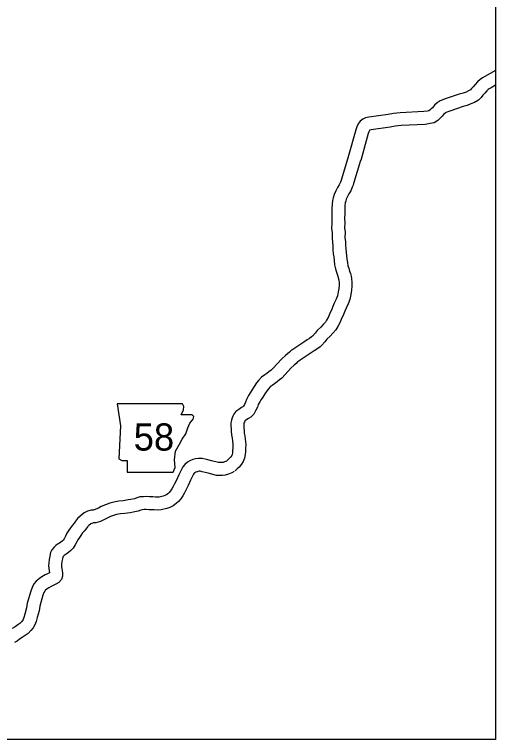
# Model space of a CAD drawing. Extents: x 1377389 to 1380723, y 1168351 to 1170484.
# Drawn here: x 1378167.1 to 1378279.2, y 1169604.3 to 1169773.2 of the extents above; entities that cross this region are included whole.
import ezdxf

# ---------------------------------------------------------------- set-up
doc = ezdxf.new("R2010")
doc.units = 0
doc.layers.add('B_Fill', color=7, linetype='Continuous')
doc.layers.add('B_Text', color=7, linetype='Continuous')

msp = doc.modelspace()

# ---------------------------------------------------------------- linework, layer by layer
at = {"layer": 'B_Fill'}
for points in [[(1378279.16, 1169760.18), (1378276.64, 1169758.77), (1378276.1, 1169758.45), (1378275.56, 1169758.08), (1378274.95, 1169757.52), (1378274.4, 1169756.89), (1378273.94, 1169756.37), (1378273.6, 1169755.97), (1378273.31, 1169755.68), (1378272.86, 1169755.41), (1378272.3, 1169755.16), (1378271.61, 1169754.91), (1378270.71, 1169754.65), (1378267.46, 1169753.55), (1378266.91, 1169753.33), (1378266.27, 1169753.08), (1378265.6, 1169752.65), (1378264.94, 1169752.07), (1378264.48, 1169751.51), (1378264.2, 1169751.21), (1378263.93, 1169750.99), (1378263.64, 1169750.81), (1378263.35, 1169750.73), (1378262.47, 1169750.6), (1378256.97, 1169750.32), (1378255.36, 1169750.14), (1378254.15, 1169749.9), (1378249.64, 1169749.31), (1378248.86, 1169749.13), (1378248.23, 1169748.84), (1378247.64, 1169748.36), (1378247.19, 1169747.73), (1378246.87, 1169747.05), (1378246.63, 1169746.37), (1378244.86, 1169740.03)], [(1378279.16, 1169756.74), (1378278.12, 1169756.16), (1378277.7, 1169755.92), (1378277.44, 1169755.74), (1378277.1, 1169755.42), (1378276.65, 1169754.91), (1378276.21, 1169754.4), (1378275.8, 1169753.92), (1378275.16, 1169753.3), (1378274.26, 1169752.76), (1378273.44, 1169752.38), (1378272.54, 1169752.05), (1378271.6, 1169751.78), (1378268.5, 1169750.74), (1378268.02, 1169750.54), (1378267.64, 1169750.39), (1378267.41, 1169750.25), (1378267.1, 1169749.97), (1378266.72, 1169749.52), (1378266.27, 1169749.05), (1378265.72, 1169748.56), (1378264.84, 1169748.02), (1378263.96, 1169747.79), (1378262.77, 1169747.61), (1378257.21, 1169747.33), (1378255.81, 1169747.17), (1378254.63, 1169746.94), (1378250.18, 1169746.36), (1378249.85, 1169746.28), (1378249.83, 1169746.28), (1378249.79, 1169746.21), (1378249.65, 1169745.92), (1378249.5, 1169745.48), (1378247.75, 1169739.23)], [(1378244.87, 1169740.07), (1378243.28, 1169734.86), (1378243.22, 1169734.64), (1378243.19, 1169734.55), (1378243.04, 1169734.19), (1378242.74, 1169733.51), (1378242.38, 1169732.91), (1378241.99, 1169732.14), (1378241.6, 1169731.28), (1378241.36, 1169730.53), (1378241.22, 1169729.91), (1378241.09, 1169729.02), (1378241.03, 1169728), (1378241.02, 1169726.83), (1378241, 1169725.73), (1378241.02, 1169724.6), (1378240.99, 1169723.39), (1378241.12, 1169722.36), (1378241.08, 1169721.07), (1378241.2, 1169720.09), (1378241.24, 1169719.37), (1378241.3, 1169718.38), (1378241.37, 1169717.47), (1378241.46, 1169716.75), (1378241.55, 1169715.9), (1378241.69, 1169714.92), (1378241.87, 1169713.95), (1378242.09, 1169713.21), (1378242.32, 1169712.49), (1378242.49, 1169711.96), (1378242.62, 1169711.53), (1378242.66, 1169711.3), (1378242.72, 1169710.67), (1378242.72, 1169710.07), (1378242.67, 1169709.37), (1378242.53, 1169708.63), (1378242.32, 1169707.7), (1378242.03, 1169706.9), (1378241.59, 1169705.96), (1378241.29, 1169705.21), (1378241, 1169704.53), (1378240.45, 1169703.38), (1378240.15, 1169702.62), (1378239.81, 1169702.01), (1378239.53, 1169701.53), (1378239.05, 1169701), (1378238.48, 1169700.38), (1378237.64, 1169699.56), (1378237.15, 1169698.94), (1378236.54, 1169698.29), (1378236.33, 1169698.09), (1378235.85, 1169697.74), (1378235.28, 1169697.39), (1378234.54, 1169696.9), (1378231.94, 1169695.16), (1378231.5, 1169694.84), (1378231.16, 1169694.58), (1378230.7, 1169694.17), (1378230.2, 1169693.73), (1378229.42, 1169692.96), (1378227.31, 1169690.73), (1378226.88, 1169690.38), (1378226.38, 1169689.94), (1378225.91, 1169689.58), (1378225.39, 1169689.23), (1378224.68, 1169688.73), (1378223.96, 1169687.95), (1378223.51, 1169687.37), (1378222.93, 1169686.53), (1378222.4, 1169685.71), (1378222.01, 1169685.09), (1378221.61, 1169684.45), (1378221.16, 1169683.55), (1378220.91, 1169682.92), (1378220.66, 1169682.36), (1378220.44, 1169681.96), (1378220.31, 1169681.83), (1378219.97, 1169681.63), (1378219.33, 1169681.18), (1378218.64, 1169680.72), (1378218.21, 1169680.11), (1378217.97, 1169679.65), (1378217.82, 1169679.24), (1378217.64, 1169678.73), (1378217.53, 1169678.04), (1378217.5, 1169677.35), (1378217.55, 1169676.67), (1378217.58, 1169676.1), (1378217.66, 1169675.29), (1378217.78, 1169674.54), (1378217.89, 1169673.9), (1378217.96, 1169672.99), (1378217.94, 1169672.22), (1378217.9, 1169671.52), (1378217.87, 1169671.04), (1378217.81, 1169670.71), (1378217.7, 1169670.45), (1378217.51, 1169670.15), (1378217.3, 1169669.89), (1378216.97, 1169669.61), (1378216.52, 1169669.18)], [(1378247.74, 1169739.19), (1378246.17, 1169734.07), (1378246.11, 1169733.83), (1378246, 1169733.49), (1378245.79, 1169733.01), (1378245.42, 1169732.14), (1378245, 1169731.44), (1378244.69, 1169730.84), (1378244.4, 1169730.2), (1378244.26, 1169729.74), (1378244.17, 1169729.36), (1378244.08, 1169728.71), (1378244.03, 1169727.9), (1378244.02, 1169726.8), (1378244, 1169725.73), (1378244.02, 1169724.58), (1378243.99, 1169723.55), (1378244.13, 1169722.51), (1378244.08, 1169721.2), (1378244.19, 1169720.35), (1378244.23, 1169719.55), (1378244.29, 1169718.6), (1378244.36, 1169717.78), (1378244.45, 1169717.08), (1378244.52, 1169716.25), (1378244.65, 1169715.41), (1378244.79, 1169714.66), (1378244.96, 1169714.09), (1378245.17, 1169713.41), (1378245.35, 1169712.88), (1378245.55, 1169712.23), (1378245.64, 1169711.68), (1378245.72, 1169710.81), (1378245.72, 1169709.96), (1378245.65, 1169709), (1378245.47, 1169708.01), (1378245.2, 1169706.85), (1378244.81, 1169705.77), (1378244.35, 1169704.76), (1378244.05, 1169704.06), (1378243.74, 1169703.3), (1378243.2, 1169702.17), (1378242.86, 1169701.34), (1378242.42, 1169700.54), (1378241.97, 1169699.76), (1378241.27, 1169698.98), (1378240.63, 1169698.29), (1378239.88, 1169697.55), (1378239.42, 1169696.97), (1378238.68, 1169696.19), (1378238.29, 1169695.81), (1378237.52, 1169695.24), (1378236.9, 1169694.87), (1378236.21, 1169694.4), (1378233.67, 1169692.71), (1378233.31, 1169692.44), (1378233.06, 1169692.26), (1378232.69, 1169691.93), (1378232.26, 1169691.54), (1378231.56, 1169690.86), (1378229.35, 1169688.52), (1378228.81, 1169688.09), (1378228.3, 1169687.63), (1378227.67, 1169687.14), (1378227.1, 1169686.76), (1378226.67, 1169686.46), (1378226.25, 1169686), (1378225.93, 1169685.6), (1378225.43, 1169684.86), (1378224.93, 1169684.09), (1378224.55, 1169683.49), (1378224.23, 1169682.98), (1378223.9, 1169682.33), (1378223.68, 1169681.76), (1378223.35, 1169681.03), (1378222.86, 1169680.12), (1378222.13, 1169679.42), (1378221.59, 1169679.1), (1378221.01, 1169678.7), (1378220.77, 1169678.54), (1378220.73, 1169678.45), (1378220.65, 1169678.22), (1378220.56, 1169677.98), (1378220.52, 1169677.73), (1378220.5, 1169677.4), (1378220.55, 1169676.86), (1378220.57, 1169676.32), (1378220.63, 1169675.67), (1378220.73, 1169675.04), (1378220.87, 1169674.28), (1378220.96, 1169673.06), (1378220.94, 1169672.1), (1378220.89, 1169671.35), (1378220.86, 1169670.67), (1378220.69, 1169669.81), (1378220.36, 1169669.06), (1378219.98, 1169668.43), (1378219.46, 1169667.78), (1378218.98, 1169667.38), (1378218.5, 1169666.91)], [(1378214.63, 1169668.82), (1378212.97, 1169669.25), (1378212.12, 1169669.47), (1378211.5, 1169669.58), (1378210.84, 1169669.76), (1378209.99, 1169669.8), (1378209.27, 1169669.71), (1378208.63, 1169669.52), (1378207.97, 1169669.23), (1378207.38, 1169668.88), (1378206.81, 1169668.4), (1378206.34, 1169667.79), (1378205.92, 1169667.07), (1378205.39, 1169665.97), (1378204.83, 1169664.71), (1378204.41, 1169663.84), (1378204.1, 1169663.23), (1378203.78, 1169662.69), (1378203.47, 1169662.24), (1378203.1, 1169661.85), (1378202.8, 1169661.54), (1378202.5, 1169661.32), (1378202.09, 1169661.11), (1378201.75, 1169660.99), (1378200.77, 1169660.75), (1378200.39, 1169660.72), (1378199.94, 1169660.77), (1378199.35, 1169660.82), (1378198.53, 1169660.84), (1378197.82, 1169660.88), (1378197.14, 1169660.85), (1378196.31, 1169660.8), (1378195.62, 1169660.58), (1378195.08, 1169660.39), (1378194.23, 1169660.19), (1378193.57, 1169660.1), (1378192.45, 1169659.91), (1378191.4, 1169659.83), (1378190.27, 1169659.62), (1378189.29, 1169659.39), (1378188.3, 1169659), (1378187.32, 1169658.55), (1378186.69, 1169658.2), (1378186.08, 1169657.92), (1378185.52, 1169657.76), (1378184.99, 1169657.72), (1378184.12, 1169657.49), (1378183.3, 1169657.13), (1378182.37, 1169656.36), (1378181.79, 1169655.78), (1378181.34, 1169655.14), (1378180.99, 1169654.71), (1378180.61, 1169654.25), (1378180.15, 1169653.63), (1378179.73, 1169653.04), (1378179.29, 1169652.33), (1378178.95, 1169651.69), (1378178.64, 1169651.08), (1378178.43, 1169650.74), (1378178.23, 1169650.54), (1378177.91, 1169650.27), (1378177.55, 1169650.03), (1378177.14, 1169649.77), (1378176.76, 1169649.46), (1378176.32, 1169649.09), (1378175.84, 1169648.45), (1378175.51, 1169647.84), (1378175.34, 1169646.99), (1378175.16, 1169646.23), (1378175.09, 1169645.49), (1378175.01, 1169644.81), (1378175.07, 1169644.11), (1378175.17, 1169643.61), (1378175.24, 1169643.21), (1378175.26, 1169643.11), (1378174.83, 1169642.89), (1378174.22, 1169642.62), (1378173.49, 1169642.17), (1378172.93, 1169641.8), (1378172.15, 1169641.16), (1378171.63, 1169640.58), (1378171.19, 1169639.68), (1378170.88, 1169638.82), (1378170.09, 1169636.04), (1378169.89, 1169634.93), (1378169.52, 1169633.5), (1378169.29, 1169632.73), (1378169.1, 1169632.21), (1378168.98, 1169631.98), (1378168.76, 1169631.73), (1378168.33, 1169631.31), (1378167.85, 1169630.97), (1378167.23, 1169630.55), (1378166.6, 1169630.12)], [(1378216.52, 1169669.17), (1378216.37, 1169669.08), (1378216.03, 1169668.95), (1378215.68, 1169668.85), (1378215.44, 1169668.83), (1378214.63, 1169668.82)], [(1378214.17, 1169665.84), (1378212.21, 1169666.35), (1378211.49, 1169666.54), (1378210.85, 1169666.64), (1378210.36, 1169666.78), (1378210.11, 1169666.79), (1378209.89, 1169666.76), (1378209.66, 1169666.69), (1378209.34, 1169666.56), (1378209.13, 1169666.43), (1378208.99, 1169666.32), (1378208.84, 1169666.11), (1378208.57, 1169665.65), (1378208.12, 1169664.72), (1378207.55, 1169663.45), (1378207.1, 1169662.51), (1378206.73, 1169661.79), (1378206.3, 1169661.06), (1378205.82, 1169660.37), (1378205.28, 1169659.78), (1378204.77, 1169659.25), (1378204.07, 1169658.75), (1378203.28, 1169658.35), (1378202.6, 1169658.11), (1378201.25, 1169657.78), (1378200.37, 1169657.71), (1378199.66, 1169657.78), (1378199.17, 1169657.82), (1378198.41, 1169657.84), (1378197.8, 1169657.88), (1378197.3, 1169657.86), (1378196.88, 1169657.83), (1378196.56, 1169657.73), (1378195.91, 1169657.5), (1378194.77, 1169657.24), (1378194.02, 1169657.14), (1378192.82, 1169656.93), (1378191.78, 1169656.85), (1378190.88, 1169656.69), (1378190.19, 1169656.52), (1378189.47, 1169656.24), (1378188.68, 1169655.88), (1378188.06, 1169655.52), (1378187.12, 1169655.1), (1378186.06, 1169654.79), (1378185.49, 1169654.75), (1378185.12, 1169654.65), (1378184.89, 1169654.55), (1378184.39, 1169654.14), (1378184.09, 1169653.84), (1378183.73, 1169653.33), (1378183.32, 1169652.82), (1378182.98, 1169652.41), (1378182.58, 1169651.86), (1378182.22, 1169651.37), (1378181.89, 1169650.84), (1378181.62, 1169650.31), (1378181.26, 1169649.62), (1378180.81, 1169648.86), (1378180.25, 1169648.32), (1378179.72, 1169647.87), (1378179.18, 1169647.51), (1378178.9, 1169647.33), (1378178.67, 1169647.15), (1378178.52, 1169647.02), (1378178.37, 1169646.82), (1378178.36, 1169646.8), (1378178.28, 1169646.36), (1378178.13, 1169645.73), (1378178.07, 1169645.18), (1378178.03, 1169644.78), (1378178.05, 1169644.54), (1378178.13, 1169644.14), (1378178.2, 1169643.7), (1378178.31, 1169643.05), (1378178.25, 1169642.34), (1378178.02, 1169641.53), (1378177.41, 1169640.85), (1378176.75, 1169640.51), (1378176.13, 1169640.18), (1378175.61, 1169639.96), (1378175.1, 1169639.64), (1378174.71, 1169639.38), (1378174.23, 1169638.99), (1378174.14, 1169638.88), (1378173.96, 1169638.52), (1378173.74, 1169637.9), (1378173.01, 1169635.36), (1378172.82, 1169634.29), (1378172.41, 1169632.7), (1378172.14, 1169631.79), (1378171.86, 1169631.01), (1378171.48, 1169630.27), (1378170.94, 1169629.66), (1378170.27, 1169629.01), (1378169.57, 1169628.51), (1378168.93, 1169628.07), (1378168.29, 1169627.64), (1378167.69, 1169627.23), (1378167.14, 1169626.86)], [(1378218.25, 1169666.72), (1378217.72, 1169666.39), (1378216.98, 1169666.1), (1378216.22, 1169665.88), (1378215.58, 1169665.83), (1378214.97, 1169665.82), (1378214.17, 1169665.84)]]:
    msp.add_lwpolyline(points, dxfattribs=at)
msp.add_lwpolyline([(1378191.01, 1169682.48), (1378191.77, 1169677.4), (1378191.43, 1169669.71), (1378192.11, 1169669.28), (1378193.38, 1169669.28), (1378193.38, 1169666.58), (1378204.04, 1169666.58), (1378204.55, 1169667.68), (1378204.38, 1169669.45), (1378204.63, 1169671.48), (1378205.56, 1169673.09), (1378206.15, 1169674.27), (1378207, 1169675.54), (1378207.51, 1169676.9), (1378207.93, 1169678), (1378208.69, 1169678.93), (1378208.86, 1169679.52), (1378208.52, 1169679.94), (1378205.9, 1169679.94), (1378206.49, 1169681.13), (1378206.58, 1169681.89), (1378206.22, 1169682.47)], close=True, dxfattribs=at)
at = {"layer": 'B_Text'}
msp.add_lwpolyline([(1377549.76, 1170388.77), (1378279.16, 1170388.77), (1378279.16, 1169604.28), (1377549.76, 1169604.28)], close=True, dxfattribs=at)

# ---------------------------------------------------------------- texts
at = {"layer": 'B_Fill'}
msp.add_text('58', height=6.336, dxfattribs=at).set_placement((1378194.87, 1169671.61))

doc.saveas('drawing.dxf')
